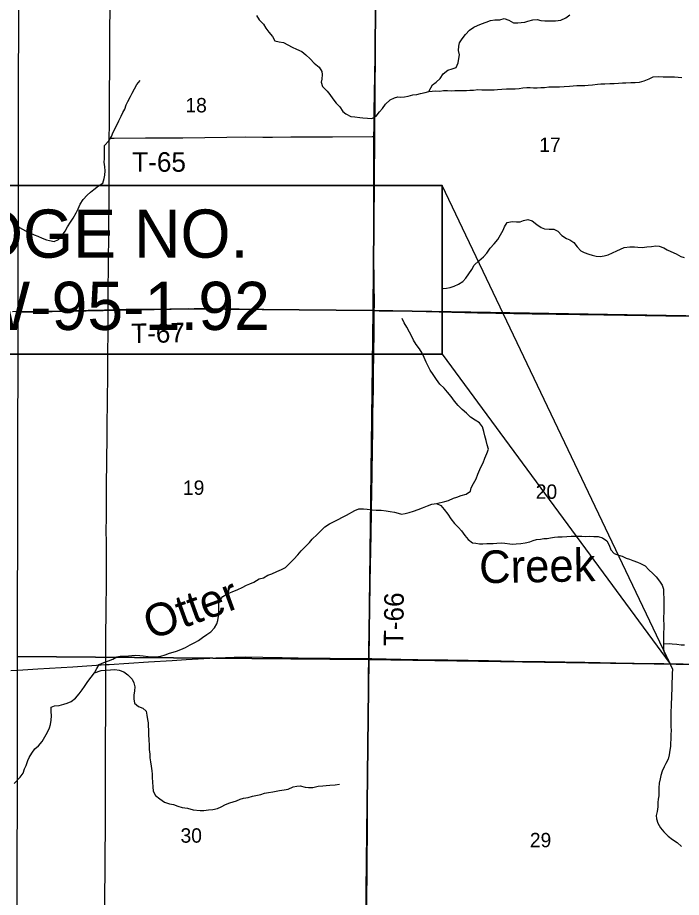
# Model space of a CAD drawing. Extents: x 0 to 34, y 0 to 22.
# Drawn here: x 2.991 to 4.92, y 17.017 to 19.573 of the extents above; entities that cross this region are included whole.
import ezdxf

# ---------------------------------------------------------------- set-up
doc = ezdxf.new("R2010")
doc.units = 0
for name, color, linetype in [('GM_X_City_Street', 7, 'Continuous'), ('GM_X_County_Road', 7, 'Continuous'), ('GM_X_County_Road_Text', 7, 'Continuous'), ('GM_X_Interchange_Ramps', 7, 'Continuous'), ('GM_X_Major_River_Text', 7, 'Continuous'), ('GM_X_Minor_River', 7, 'Continuous'), ('GM_X_Rail_Line', 7, 'Continuous'), ('GM_X_Section', 7, 'Continuous'), ('GM_X_Unincorporated_Location', 7, 'Continuous'), ('SH_Border', 7, 'Continuous'), ('SH_Cut_Line', 7, 'Continuous')]:
    doc.layers.add(name, color=color, linetype=linetype)

msp = doc.modelspace()

# ---------------------------------------------------------------- linework, layer by layer
at = {"layer": 'GM_X_City_Street'}
msp.add_lwpolyline([(4.0025, 16.7029), (4.0027, 16.7213), (4.0033, 16.7679), (4.0037, 16.8145), (4.0046, 16.9356), (4.0053, 17.004), (4.0062, 17.0972), (4.0066, 17.15), (4.0072, 17.1841), (4.0076, 17.2059), (4.0077, 17.2431), (4.0078, 17.3053), (4.0084, 17.3612), (4.0087, 17.4016), (4.0091, 17.4326), (4.0093, 17.4823), (4.0097, 17.5258), (4.0103, 17.5848), (4.0105, 17.619), (4.0108, 17.6594), (4.0111, 17.7107)], dxfattribs=at)
at = {"layer": 'GM_X_County_Road'}
for points in [[(2.971, 17.6764), (3.0056, 17.6782), (3.049, 17.6806), (3.1514, 17.687), (3.247, 17.6933), (3.2568, 17.6939), (3.3715, 17.7012), (3.4398, 17.7053), (3.4801, 17.7077), (3.5669, 17.7128), (3.5949, 17.7143), (3.6198, 17.7152), (3.654, 17.7153), (3.7037, 17.7147), (3.7596, 17.7137), (3.8062, 17.7131), (3.8994, 17.7119), (4.0111, 17.7107), (4.0206, 17.7106), (4.1045, 17.7094), (4.1542, 17.7083), (4.2412, 17.7069), (4.3002, 17.7058), (4.3593, 17.7049), (4.4338, 17.7034), (4.5239, 17.7021), (4.6389, 17.7001), (4.729, 17.6983), (4.7787, 17.6977), (4.7827, 17.6976)], [(4.7827, 17.6976), (4.8688, 17.696), (4.9247, 17.6952), (4.9436, 17.6949)]]:
    msp.add_lwpolyline(points, dxfattribs=at)
at = {"layer": 'GM_X_Interchange_Ramps'}
for points in [[(3.2571, 19.2226), (3.2573, 19.2619), (3.2575, 19.3241), (3.2579, 19.3707), (3.2582, 19.4111), (3.2586, 19.4919), (3.2588, 19.5385), (3.2594, 19.5975), (3.2598, 19.669), (3.2599, 19.7187), (3.2599, 19.7293)], [(4.0274, 18.7218), (4.0275, 18.7368), (4.027, 18.8052), (4.0264, 18.8767), (4.0262, 19.0228), (4.0262, 19.0726), (4.0257, 19.1099), (4.026, 19.1316), (4.026, 19.1502), (4.0258, 19.1627), (4.0256, 19.1875), (4.0265, 19.2248), (4.0265, 19.2282), (4.0267, 19.2559), (4.0271, 19.2963), (4.0281, 19.3584), (4.0285, 19.3989), (4.0298, 19.4672), (4.0313, 19.5854), (4.0325, 19.66), (4.0338, 19.7253), (4.0339, 19.7324)], [(3.2571, 19.2226), (3.2609, 19.2226), (3.2717, 19.2226), (3.362, 19.2236), (3.4709, 19.2243), (3.5985, 19.2254), (3.6542, 19.2263), (3.7038, 19.226), (3.7316, 19.2262), (3.7844, 19.2271), (3.8312, 19.2266), (3.9059, 19.227), (4.0211, 19.2281), (4.0265, 19.2282)], [(3.2538, 18.7242), (3.2538, 18.7462), (3.2537, 18.771), (3.254, 18.799), (3.2545, 18.8332), (3.2551, 18.8829), (3.2555, 18.9233), (3.256, 18.9792), (3.2563, 19.0196), (3.2564, 19.0569), (3.2567, 19.1128), (3.257, 19.1718), (3.257, 19.206), (3.2571, 19.2226)], [(2.9755, 18.7194), (3.0788, 18.7203), (3.1471, 18.7218), (3.2434, 18.7239), (3.2538, 18.7242)], [(3.2487, 18.1779), (3.2488, 18.1839), (3.2492, 18.2212), (3.2493, 18.2368), (3.2497, 18.2615), (3.2501, 18.2957), (3.2506, 18.3454), (3.251, 18.3889), (3.2514, 18.4572), (3.2519, 18.4821), (3.2524, 18.5131), (3.2532, 18.6001), (3.2534, 18.6561), (3.2537, 18.6871), (3.2538, 18.7182), (3.2538, 18.7242)], [(3.2538, 18.7242), (3.3118, 18.7258), (3.4329, 18.727), (3.5042, 18.7282), (3.5446, 18.7282), (3.6347, 18.7272), (3.7062, 18.7259), (3.7621, 18.7253), (3.8212, 18.7244), (3.9703, 18.7227), (4.0274, 18.7218)], [(4.0111, 17.7107), (4.0112, 17.7172), (4.0118, 17.7389), (4.0127, 17.7855), (4.0141, 17.8508), (4.0156, 17.9348), (4.0163, 17.9783), (4.017, 18.028), (4.0178, 18.0684), (4.0195, 18.143), (4.0205, 18.1959), (4.0212, 18.2456), (4.0223, 18.3233), (4.0225, 18.3389), (4.0227, 18.3544), (4.0235, 18.4228), (4.024, 18.457), (4.0247, 18.4943), (4.0254, 18.5378), (4.0261, 18.5969), (4.0271, 18.6591), (4.0274, 18.687), (4.0274, 18.7218)], [(4.0274, 18.7218), (4.0418, 18.7216), (4.1008, 18.7207), (4.1785, 18.7188), (4.3276, 18.7156), (4.486, 18.7127), (4.6942, 18.7096), (4.8744, 18.7071), (4.9676, 18.7057), (5.0471, 18.7054), (5.05, 18.7053)], [(3.247, 17.6933), (3.247, 17.6992), (3.2471, 17.7334), (3.2473, 17.7893), (3.2477, 17.8328), (3.2485, 17.9509), (3.2485, 18.0503), (3.2482, 18.0814), (3.2486, 18.1218), (3.2487, 18.1779)], [(3.2423, 16.7102), (3.2424, 16.7422), (3.2427, 16.8199), (3.2432, 16.8665), (3.2439, 16.9504), (3.2441, 17.0032), (3.2443, 17.0405), (3.2447, 17.0746), (3.2451, 17.1399), (3.2457, 17.2176), (3.2457, 17.2673), (3.2461, 17.3605), (3.2463, 17.4196), (3.2464, 17.4631), (3.2467, 17.5625), (3.247, 17.6495), (3.247, 17.6806), (3.247, 17.6933)], [(4.0025, 16.7029), (4.0027, 16.7213), (4.0033, 16.7679), (4.0037, 16.8145), (4.0046, 16.9356), (4.0053, 17.004), (4.0062, 17.0972), (4.0066, 17.15), (4.0072, 17.1841), (4.0076, 17.2059), (4.0077, 17.2431), (4.0078, 17.3053), (4.0084, 17.3612), (4.0087, 17.4016), (4.0091, 17.4326), (4.0093, 17.4823), (4.0097, 17.5258), (4.0103, 17.5848), (4.0105, 17.619), (4.0108, 17.6594), (4.0111, 17.7107)]]:
    msp.add_lwpolyline(points, dxfattribs=at)
at = {"layer": 'GM_X_Rail_Line'}
msp.add_lwpolyline([(2.489, 19.0856), (4.2244, 19.0856), (4.2244, 18.5956), (2.489, 18.5956)], close=True, dxfattribs=at)
at = {"layer": 'GM_X_Section'}
for points in [[(3.6849, 19.5796), (3.6929, 19.5671), (3.7054, 19.5546), (3.7123, 19.5421), (3.7211, 19.5311), (3.7317, 19.5183), (3.7386, 19.5054), (3.7508, 19.5024), (3.7633, 19.5006), (3.7891, 19.4878), (3.8017, 19.4817), (3.8165, 19.4746), (3.8283, 19.4648), (3.8405, 19.4534), (3.853, 19.4409), (3.8667, 19.4292), (3.8751, 19.4171), (3.8755, 19.4076), (3.8752, 19.3947), (3.873, 19.3853), (3.8764, 19.3728), (3.8905, 19.3599), (3.8981, 19.3501), (3.9073, 19.3376), (3.9168, 19.3243), (3.9275, 19.3141), (3.9355, 19.3005), (3.945, 19.2937), (3.9587, 19.2858), (3.9712, 19.2847), (3.9849, 19.2832), (3.9943, 19.2821), (4.0072, 19.2807), (4.0198, 19.2796), (4.0326, 19.2868), (4.0428, 19.2998), (4.0511, 19.3093), (4.0602, 19.3214), (4.0738, 19.3344), (4.0859, 19.3401), (4.0954, 19.3428), (4.1049, 19.3421), (4.1151, 19.3429), (4.1261, 19.3452), (4.1398, 19.3486), (4.1508, 19.3502), (4.1618, 19.3525), (4.175, 19.3556), (4.1856, 19.3586), (4.1951, 19.3598), (4.2046, 19.3606), (4.2175, 19.3599), (4.2289, 19.3611), (4.2406, 19.3615), (4.252, 19.3604), (4.2615, 19.3612), (4.2843, 19.3613), (4.2953, 19.3617), (4.3048, 19.3621), (4.3158, 19.3621), (4.3286, 19.3641), (4.3397, 19.3637), (4.3491, 19.3634), (4.3613, 19.363), (4.3757, 19.3635), (4.3852, 19.3646), (4.3981, 19.3654), (4.4117, 19.3659), (4.4216, 19.3659), (4.4368, 19.3667), (4.4485, 19.3675), (4.4591, 19.3694), (4.4705, 19.3699), (4.4804, 19.3703), (4.4899, 19.3695), (4.5012, 19.3696), (4.5111, 19.37), (4.5217, 19.3704), (4.5346, 19.3716), (4.546, 19.372), (4.5562, 19.372), (4.5661, 19.3725), (4.5794, 19.3733), (4.5945, 19.3741), (4.6052, 19.3752), (4.6158, 19.3757), (4.626, 19.3761), (4.6393, 19.3757), (4.6492, 19.3765), (4.6613, 19.3777), (4.6757, 19.38), (4.6856, 19.3804), (4.6977, 19.3809), (4.7121, 19.3821)], [(4.1856, 19.3586), (4.1966, 19.3776), (4.2068, 19.3856), (4.2189, 19.3963), (4.2276, 19.41), (4.2412, 19.4203), (4.2537, 19.4241), (4.2658, 19.4283), (4.2715, 19.4416), (4.2733, 19.4545), (4.2752, 19.4655), (4.2725, 19.478), (4.2728, 19.4905), (4.2754, 19.5), (4.2826, 19.5118), (4.2924, 19.524), (4.3038, 19.5369), (4.317, 19.5453), (4.3276, 19.5507), (4.3386, 19.5556), (4.3526, 19.5595), (4.3651, 19.5648), (4.378, 19.5668), (4.392, 19.5668), (4.4049, 19.5706), (4.4186, 19.5661), (4.4319, 19.5582), (4.4448, 19.5579), (4.4543, 19.5591), (4.4645, 19.5598), (4.474, 19.5629), (4.488, 19.5671), (4.5009, 19.5676), (4.5115, 19.5646), (4.5226, 19.5638), (4.5442, 19.5639), (4.5544, 19.5636), (4.5692, 19.5659), (4.584, 19.5724), (4.5961, 19.5815)], [(2.9875, 18.9685), (3.0137, 18.9534), (3.0259, 18.9478), (3.0384, 18.9417), (3.0491, 18.938), (3.062, 18.9323), (3.0741, 18.9278), (3.0836, 18.9252), (3.0973, 18.923), (3.109, 18.9283), (3.1192, 18.9394), (3.1287, 18.9523), (3.1358, 18.9648), (3.1441, 18.9789), (3.1524, 18.9907), (3.1607, 19.0063), (3.1668, 19.018), (3.1724, 19.0313), (3.1807, 19.0446), (3.1924, 19.0576), (3.2023, 19.0663), (3.2121, 19.0739), (3.2257, 19.0842), (3.2382, 19.0922), (3.2423, 19.1055), (3.2438, 19.115), (3.2449, 19.1275), (3.2445, 19.14), (3.2425, 19.1533), (3.2433, 19.1632), (3.2432, 19.1749), (3.2428, 19.1886), (3.2435, 19.2018), (3.2556, 19.2148), (3.2635, 19.2277), (3.2684, 19.2406), (3.2737, 19.2509), (3.2846, 19.2729), (3.2914, 19.2873), (3.2963, 19.2972), (3.3019, 19.3071), (3.3064, 19.3196), (3.3109, 19.3299), (3.3192, 19.3436), (3.3238, 19.3534), (3.3302, 19.366), (3.3369, 19.3785), (3.3471, 19.3907)], [(4.7121, 19.3821), (4.7243, 19.3813), (4.7368, 19.3829), (4.7485, 19.3837), (4.7588, 19.3841), (4.7728, 19.3845), (4.7857, 19.385), (4.7986, 19.3858), (4.8122, 19.3896), (4.8259, 19.3953), (4.8384, 19.4007), (4.8524, 19.4019), (4.8668, 19.4008), (4.8763, 19.4012), (4.8892, 19.4016), (4.8998, 19.4013), (4.9108, 19.4002), (4.9214, 19.3994)], [(4.2279, 18.7857), (4.2374, 18.7873), (4.248, 18.7888), (4.2597, 18.7927), (4.2722, 18.7988), (4.2847, 18.806), (4.2934, 18.8159), (4.3021, 18.8285), (4.3104, 18.841), (4.3179, 18.8535), (4.3312, 18.8669), (4.3444, 18.8779), (4.3542, 18.8886), (4.3637, 18.903), (4.3761, 18.9156), (4.3867, 18.9289), (4.3946, 18.9422), (4.4018, 18.9551), (4.4059, 18.9657), (4.4139, 18.9775), (4.4279, 18.981), (4.4404, 18.9795), (4.451, 18.9799), (4.4609, 18.9837), (4.4734, 18.9864), (4.4863, 18.9823), (4.4996, 18.9725), (4.5125, 18.9634), (4.5224, 18.9593), (4.5361, 18.9586), (4.5493, 18.9582), (4.5611, 18.9526), (4.5729, 18.9397), (4.5862, 18.9318), (4.5957, 18.9273), (4.6075, 18.9194), (4.6171, 18.9073), (4.6277, 18.8956), (4.6376, 18.8903), (4.6505, 18.8858), (4.6608, 18.8828), (4.6722, 18.8798), (4.6843, 18.8794), (4.6957, 18.8814), (4.7067, 18.8841), (4.7199, 18.8894), (4.7328, 18.8959), (4.7426, 18.9005), (4.7536, 18.9055), (4.7699, 18.9067), (4.784, 18.9067), (4.7938, 18.9064), (4.806, 18.9053), (4.82, 18.9068), (4.8329, 18.9084), (4.8458, 18.9096), (4.8557, 18.9088), (4.8689, 18.9043), (4.8788, 18.8983), (4.8895, 18.8938), (4.905, 18.887), (4.9184, 18.8787), (4.9282, 18.8757)], [(4.2081, 18.161), (4.2324, 18.1668), (4.2426, 18.1699), (4.2577, 18.1764), (4.2676, 18.1802), (4.2801, 18.1844), (4.2941, 18.1886), (4.307, 18.197), (4.3092, 18.2065), (4.3156, 18.219), (4.3235, 18.2331), (4.3284, 18.2464), (4.3344, 18.2597), (4.3378, 18.2692), (4.3435, 18.2794), (4.3484, 18.2931), (4.3544, 18.3064), (4.3589, 18.3193), (4.3558, 18.3322), (4.3527, 18.3447), (4.3485, 18.3576), (4.3462, 18.3705), (4.342, 18.3841), (4.3328, 18.3958), (4.3203, 18.4034), (4.3074, 18.4121), (4.2956, 18.4238), (4.2826, 18.434), (4.2712, 18.4457), (4.2601, 18.4585), (4.2506, 18.4722), (4.24, 18.485), (4.23, 18.4967), (4.2182, 18.5085), (4.208, 18.5217), (4.1988, 18.5357), (4.19, 18.5489), (4.1832, 18.5626), (4.1786, 18.5724), (4.1724, 18.5857), (4.1663, 18.5978), (4.1583, 18.6107), (4.1488, 18.6231), (4.1415, 18.6364), (4.1366, 18.6466), (4.1297, 18.6595), (4.1221, 18.6735), (4.1144, 18.6867), (4.1079, 18.6992)], [(4.0469, 18.1419), (4.0614, 18.14), (4.0739, 18.1382), (4.0857, 18.136), (4.097, 18.133), (4.1065, 18.1307), (4.1168, 18.1319), (4.1289, 18.135), (4.1418, 18.1392), (4.1547, 18.1438), (4.1679, 18.1491), (4.1816, 18.1549), (4.1948, 18.1591), (4.2081, 18.161), (4.221, 18.1558), (4.2309, 18.1437), (4.2412, 18.1304), (4.25, 18.1164), (4.2606, 18.1032), (4.2724, 18.0918), (4.2812, 18.0816), (4.2907, 18.0688), (4.3003, 18.0563), (4.3128, 18.0468), (4.3227, 18.0457), (4.3329, 18.0446), (4.3432, 18.0443), (4.3542, 18.0447), (4.3731, 18.0451), (4.3838, 18.0459), (4.3967, 18.0467), (4.4069, 18.0456), (4.4209, 18.0442), (4.4304, 18.0434), (4.4399, 18.0446), (4.4536, 18.045), (4.4661, 18.0466), (4.479, 18.0501), (4.4892, 18.0539), (4.499, 18.0566), (4.51, 18.0581), (4.5199, 18.0593), (4.5301, 18.0601), (4.5396, 18.0613), (4.551, 18.0632), (4.5609, 18.064), (4.5737, 18.0648), (4.5866, 18.0652), (4.5999, 18.0664), (4.6109, 18.0668), (4.6208, 18.0665), (4.6303, 18.0661), (4.6424, 18.0658), (4.6523, 18.0662), (4.6655, 18.0659), (4.6781, 18.0651), (4.691, 18.0614), (4.7028, 18.0531), (4.7104, 18.0402), (4.7146, 18.0266), (4.7249, 18.016), (4.7374, 18.0115), (4.7477, 18.0081), (4.7598, 18.0025), (4.7693, 17.9991), (4.7792, 17.9957), (4.7921, 17.9908), (4.8016, 17.9867), (4.8149, 17.9803), (4.8256, 17.9682), (4.8366, 17.9576), (4.8465, 17.9478), (4.8564, 17.936), (4.8644, 17.9243), (4.8679, 17.9126), (4.8683, 17.9), (4.8691, 17.8864), (4.8692, 17.8769), (4.8688, 17.8671), (4.8685, 17.8538), (4.8685, 17.8443), (4.8682, 17.8314), (4.8682, 17.8215), (4.8686, 17.8121), (4.8687, 17.7992), (4.8683, 17.7859), (4.868, 17.7749), (4.8684, 17.7628), (4.8681, 17.7533), (4.8677, 17.7419), (4.8693, 17.7305), (4.8754, 17.7169), (4.8823, 17.7048), (4.8888, 17.6927), (4.8938, 17.6802), (4.8934, 17.6669), (4.8931, 17.6544), (4.8924, 17.6419), (4.8924, 17.6202), (4.8917, 17.6077), (4.8914, 17.5948)], [(2.9802, 17.3473), (2.9985, 17.3662), (3.0065, 17.378), (3.011, 17.3901), (3.0151, 17.4), (3.0207, 17.4141), (3.0245, 17.4235), (3.0324, 17.4361), (3.0407, 17.4483), (3.0509, 17.457), (3.0623, 17.4699), (3.0702, 17.4829), (3.0773, 17.4969), (3.0834, 17.5098), (3.0864, 17.5193), (3.0882, 17.5322), (3.0893, 17.5444), (3.0885, 17.5565), (3.0885, 17.5694), (3.0983, 17.5732), (3.1116, 17.5744), (3.1249, 17.5779), (3.1343, 17.5809), (3.1461, 17.5859), (3.1593, 17.5954), (3.1695, 17.6084), (3.1782, 17.6198), (3.1854, 17.63), (3.1952, 17.6437), (3.2042, 17.6566), (3.2141, 17.6688), (3.2205, 17.6821), (3.2272, 17.6935), (3.2413, 17.6992), (3.2549, 17.7038), (3.2674, 17.7092), (3.2791, 17.7153), (3.289, 17.7176), (3.2996, 17.718), (3.3129, 17.7188), (3.3227, 17.7196), (3.3322, 17.7208), (3.3459, 17.7201), (3.3554, 17.7182), (3.3702, 17.7164), (3.3835, 17.716), (3.3937, 17.7161), (3.407, 17.718), (3.4195, 17.7215), (3.432, 17.726), (3.443, 17.7295), (3.4524, 17.7326), (3.4653, 17.7372), (3.4786, 17.7429), (3.4926, 17.7509), (3.5055, 17.7574), (3.5168, 17.7635), (3.5285, 17.7719), (3.541, 17.7806), (3.5524, 17.7886), (3.5633, 17.8001), (3.5698, 17.8118), (3.5724, 17.8213), (3.5742, 17.8342), (3.5753, 17.8445), (3.5757, 17.8574), (3.5752, 17.8699), (3.5779, 17.8798), (3.5873, 17.8912), (3.5994, 17.8988), (3.6142, 17.9045), (3.6305, 17.9118), (3.643, 17.9175), (3.6558, 17.9236), (3.6657, 17.9275), (3.6774, 17.9328), (3.6926, 17.942), (3.7051, 17.9458), (3.7183, 17.9527), (3.7297, 17.9565), (3.7437, 17.9638), (3.7573, 17.9695), (3.7695, 17.9752), (3.7823, 17.9878), (3.7933, 17.9996), (3.8054, 18.0117), (3.8152, 18.0239), (3.839, 18.0479), (3.8466, 18.0574), (3.8613, 18.0711), (3.8836, 18.0936), (3.8969, 18.1023), (3.9105, 18.1088), (3.9468, 18.1271), (3.9707, 18.1405), (3.9824, 18.1455), (3.9961, 18.1459), (4.0067, 18.1448), (4.0215, 18.1426), (4.0329, 18.1415), (4.0469, 18.1419)], [(4.8681, 17.7533), (4.884, 17.7541), (4.8935, 17.7537), (4.9068, 17.7523), (4.9189, 17.7504), (4.9292, 17.7508)], [(3.2141, 17.6688), (3.233, 17.6757), (3.2459, 17.6769), (3.2603, 17.6784), (3.2732, 17.6789), (3.2861, 17.6774), (3.2994, 17.6721), (3.3112, 17.6638), (3.3234, 17.651), (3.3287, 17.6404), (3.331, 17.6286), (3.3299, 17.6169), (3.3288, 17.604), (3.3281, 17.5933), (3.3301, 17.5816), (3.3422, 17.5714), (3.3544, 17.5669), (3.3643, 17.5582), (3.3662, 17.5461), (3.3686, 17.5335), (3.3697, 17.5241), (3.3705, 17.5146), (3.3713, 17.5036), (3.3714, 17.4888), (3.3718, 17.4744), (3.373, 17.4589), (3.3734, 17.4467), (3.3746, 17.4334), (3.375, 17.4224), (3.3766, 17.4107), (3.3785, 17.3978), (3.3808, 17.3849), (3.382, 17.3747), (3.3821, 17.3648), (3.3825, 17.3516), (3.384, 17.3383), (3.3849, 17.3258), (3.391, 17.3133), (3.4039, 17.3035), (3.4172, 17.2936), (3.4324, 17.2888), (3.4442, 17.2865), (3.4559, 17.282), (3.4692, 17.2779), (3.484, 17.2757), (3.5007, 17.2712), (3.5212, 17.269), (3.5315, 17.2694), (3.5451, 17.2713), (3.558, 17.2717), (3.5713, 17.2748), (3.5827, 17.2802), (3.5951, 17.2867), (3.6073, 17.2912), (3.6171, 17.2947), (3.6266, 17.2978), (3.6376, 17.3023), (3.6471, 17.305), (3.6603, 17.307), (3.6732, 17.3108), (3.6876, 17.3135), (3.6971, 17.3158), (3.7081, 17.3193), (3.7198, 17.3216), (3.732, 17.3231), (3.7418, 17.3258), (3.7517, 17.3278), (3.7657, 17.3289), (3.7767, 17.3316), (3.7918, 17.3385), (3.8025, 17.3401), (3.8119, 17.3405), (3.8267, 17.3375), (3.8362, 17.3356), (3.8491, 17.3357), (3.8639, 17.3399), (3.8776, 17.3411), (3.8874, 17.3423), (3.8984, 17.343), (3.9132, 17.3439), (3.9261, 17.3458)], [(4.8914, 17.5948), (4.8899, 17.5819), (4.89, 17.5721), (4.8893, 17.5569), (4.8893, 17.547), (4.8893, 17.5372), (4.8897, 17.5265), (4.8894, 17.5144), (4.8898, 17.5008), (4.8895, 17.4909), (4.8892, 17.4761), (4.8888, 17.4651), (4.8881, 17.4552), (4.8866, 17.445), (4.8844, 17.431), (4.8814, 17.4188), (4.8746, 17.4059), (4.8697, 17.3964), (4.8645, 17.3835), (4.8603, 17.3706), (4.8581, 17.3611), (4.8555, 17.3482), (4.8548, 17.3349), (4.8548, 17.3247), (4.8541, 17.3114), (4.8526, 17.3019), (4.8515, 17.2924), (4.8512, 17.2795), (4.8493, 17.2666), (4.8471, 17.2545), (4.8475, 17.2446), (4.8517, 17.2321), (4.859, 17.2185), (4.8685, 17.2075), (4.8818, 17.195), (4.894, 17.1852), (4.9073, 17.1762), (4.9206, 17.1648)]]:
    msp.add_lwpolyline(points, dxfattribs=at)
at = {"layer": 'GM_X_Unincorporated_Location'}
for points in [[(2.9937, 19.7212), (3.5973, 19.7312), (4.0319, 19.7295), (4.0237, 18.7217), (3.4868, 18.7265), (2.9925, 18.7172)], [(4.0319, 19.7295), (5.0575, 19.7147), (5.0466, 18.7043), (4.0237, 18.7217)], [(2.9925, 18.7172), (3.4868, 18.7265), (4.0237, 18.7217), (4.0116, 17.7079), (2.9907, 17.7166)], [(4.0237, 18.7217), (5.0466, 18.7043), (5.0326, 17.6924), (4.0116, 17.7079)], [(4.0116, 17.7079), (3.9996, 16.6997), (2.9891, 16.7122), (2.9907, 17.7166)], [(5.0326, 17.6924), (5.0069, 16.682), (3.9996, 16.6997), (4.0116, 17.7079)]]:
    msp.add_lwpolyline(points, close=True, dxfattribs=at)
at = {"layer": 'SH_Border'}
for points in [[(2.489, 18.5956), (4.2244, 18.5956), (4.2244, 19.0856), (2.489, 19.0856)], [(4.8871, 17.6958), (4.2244, 19.0856), (4.2244, 18.5956)]]:
    msp.add_lwpolyline(points, close=True, dxfattribs=at)
at = {"layer": 'SH_Cut_Line'}
msp.add_line((4.863, 17.6962), (4.908, 17.6954), dxfattribs=at)

# ---------------------------------------------------------------- texts
at = {"layer": 'GM_X_County_Road_Text'}
for s, rotation, p in [('T-65', 0, (3.3237, 19.1253)), ('T-67', 1.0663, (3.3211, 18.627)), ('T-66', 89.2952, (4.1115, 17.7464))]:
    msp.add_text(s, height=0.05682, rotation=rotation, dxfattribs=at).set_placement(p)
at = {"layer": 'GM_X_Major_River_Text'}
for s, p in [('18', (3.4783, 19.2978)), ('17', (4.507, 19.1829)), ('19', (3.4712, 18.1865)), ('20', (4.4966, 18.1749)), ('30', (3.4641, 17.1757)), ('29', (4.4795, 17.1624))]:
    msp.add_text(s, height=0.04186, rotation=0, dxfattribs=at).set_placement(p)
at = {"layer": 'GM_X_Minor_River'}
for s, rotation, p in [('Creek', 1.0804, (4.333, 17.9294)), ('Otter', 19.9751, (3.3779, 17.7645))]:
    msp.add_text(s, height=0.09472, rotation=rotation, dxfattribs=at).set_placement(p)
at = {"layer": 'SH_Border'}
for s, p in [('BRIDGE NO. ', (2.559, 18.8756)), ('MRW-95-1.92', (2.559, 18.6656))]:
    msp.add_text(s, height=0.14, dxfattribs=at).set_placement(p)

doc.saveas('drawing.dxf')
